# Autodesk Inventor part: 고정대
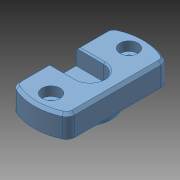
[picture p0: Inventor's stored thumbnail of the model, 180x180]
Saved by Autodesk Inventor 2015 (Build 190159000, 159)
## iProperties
Created: 2023-11
Part Number: 고정대
Material: 강철, 탄소
Document SubType Name: Modeling
Designer: mdu-01
Density: 1 g/cm^3
Appearance: 기본값(1)
Author: mdu-01
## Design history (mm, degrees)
sketch "스케치1"
  geometry: L1 (10, -15.492)-(10, 15.492); L2 (-10, -15.492)-(-10, 15.492); A1 r 20 centre (0, 0) between (8.235, 18.226) and (-8.235, 18.226); A2 r 20 centre (0, 0) between (-8.235, -18.226) and (8.235, -18.226); A3 r 3 centre (7, -15.492) between (8.235, -18.226) and (10, -15.492); A4 r 3 centre (-7, -15.492) between (-10, -15.492) and (-8.235, -18.226); A5 r 3 centre (7, 15.492) between (10, 15.492) and (8.235, 18.226); A6 r 3 centre (-7, 15.492) between (-8.235, 18.226) and (-10, 15.492); 5 further points
  constraints: 16 point on circle, 8 tangent, 6 centre point, 4 end point, 4 point on line, 3 equal radius, 1 coincident, 1 horizontal alignment, 1 parallel, 1 vertical
  dimensions: "d1" = 20 distance between parallel lines of L2 L1; "d2" = 20 radius of A1; "d3" = 3 radius of A3; "d6" = 3 radius of A6
extrude "돌출1" new body sketch "스케치1" distance "d4" = 8; taper "d5" = 0 deg
sketch "스케치2"
  geometry: C1 r 8 at (0, 0); 1 further point
  constraints: 1 centre point, 1 coincident
  dimensions: "d7" = 16 diameter of C1
extrude "돌출2" join sketch "스케치2" distance "d8" = 4; taper "d9" = 0 deg
chamfer "모따기1" distance "d10" = 1; stored, may be unused: second distance "d11" = 2, angle "d12" = 45 deg
sketch "스케치3"
  geometry: L1 (0, 5)-(-10, 5); L2 (-10, 5)-(-10, -5); L3 (-10, -5)-(0, -5); L4 (-10, 15.492)-(-10, -15.492) reference; A1 r 5 centre (0, 0) between (0, -5) and (0, 5); 1 further point
  constraints: 6 end point, 2 horizontal, 2 point on circle, 2 tangent, 1 centre point, 1 coincident, 1 collinear, 1 perpendicular
  dimensions: "d13" = 10 diameter of A1
extrude "돌출3" cut sketch "스케치3" distance "d14" = 6; taper "d15" = 0 deg
chamfer "모따기2" distance "d16" = 0.5; stored, may be unused: second distance "d17" = 2, angle "d18" = 45 deg
sketch "스케치4"
  geometry: C1 r 1.23 at (0, 14) reference; C2 r 1.23 at (0, -14) reference; 1 further point
hole "구멍1" sketch "스케치4" at (0, 14), (0, -14) diameter "d19" = 3.4; stored, may be unused: countersink angle "d23" = 90 deg, drill point angle "d25" = 118 deg; dims "d20" = 6, "d21" = 6.5, "d22" = 5, "d24" = 8
node "솔리드1"
node "참조1"
node "참조2"
